(* Logix 5000 project; controller eNod4TSample vendor 1 type 14 code 106 rev 28.12; software revision 28.00; part 2 of 2 *)
(* tags used below, declared in another part *)
   Datas : TeNod4TDatas;
   DatasOUT : SINT[2];
   Command : INT;
   Ready : BOOL;
   Done : BOOL;
   Timeout : BOOL;
   StabWeight : DINT;
   StabTime : DINT;
   Stability : BOOL;
   LoopWStart : BOOL;
   LoopWStartEdge : BOOL;
   LoopWRun : BOOL;
   LoopWSend : BOOL;
   LoopWDone : BOOL;
   MemCounter : DINT;
   TimerOut : TIMER;
   TimerStab : TIMER;
   MemNet : DINT;
   StabOK : BOOL;
(* TeNod4TBlocMain, continued *)

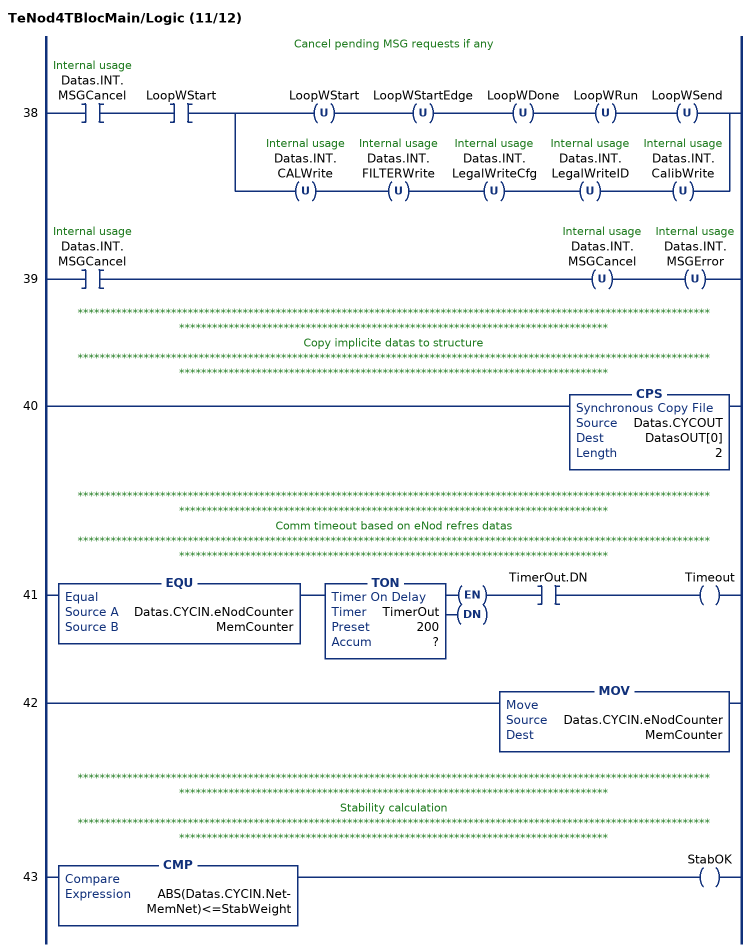
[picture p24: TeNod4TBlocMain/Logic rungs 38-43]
   // Cancel pending MSG requests if any
   38: XIC(Datas.INT.MSGCancel)XIC(LoopWStart)[OTU(LoopWStart) OTU(LoopWStartEdge) OTU(LoopWDone) OTU(LoopWRun) OTU(LoopWSend) ,OTU(Datas.INT.CALWrite) OTU(Datas.INT.FILTERWrite) OTU(Datas.INT.LegalWriteCfg) OTU(Datas.INT.LegalWriteID) OTU(Datas.INT.CalibWrite) ];
   39: XIC(Datas.INT.MSGCancel)OTU(Datas.INT.MSGCancel)OTU(Datas.INT.MSGError);
   // *************************************************************************************************************************************************************************************************
   // Copy implicite datas to structure
   // *************************************************************************************************************************************************************************************************
   40: CPS(Datas.CYCOUT,DatasOUT[0],2);
   // *************************************************************************************************************************************************************************************************
   // Comm timeout based on eNod refres datas
   // *************************************************************************************************************************************************************************************************
   41: EQU(Datas.CYCIN.eNodCounter,MemCounter)TON(TimerOut,?,?)XIC(TimerOut.DN)OTE(Timeout);
   42: MOV(Datas.CYCIN.eNodCounter,MemCounter);
   // *************************************************************************************************************************************************************************************************
   // Stability calculation
   // *************************************************************************************************************************************************************************************************
   43: CMP(ABS(Datas.CYCIN.Net-MemNet)<=StabWeight)OTE(StabOK);
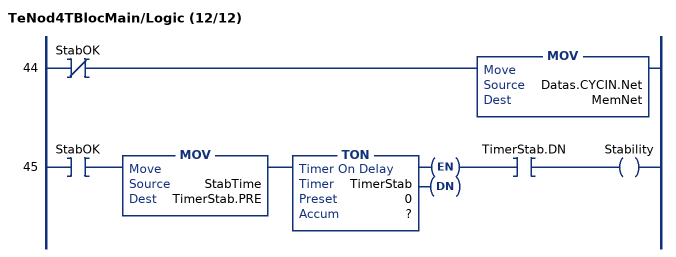
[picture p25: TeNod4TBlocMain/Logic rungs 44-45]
   44: XIO(StabOK)MOV(Datas.CYCIN.Net,MemNet);
   45: XIC(StabOK)MOV(StabTime,TimerStab.PRE)TON(TimerStab,?,?)XIC(TimerStab.DN)OTE(Stability);
END_ROUTINE
END_ADD_ON_INSTRUCTION

VAR_GLOBAL   (* controller tags *)
   Scale1Datas : TeNod4TDatas;
   Scale1R : MESSAGE;
        MessageParameters(ServiceCode := 16#000e, DestinationTag := Scale1Datas.MSGBuffer, ...)
   Scale1W : MESSAGE;
        MessageParameters(ServiceCode := 16#0010, LocalElement := Scale1Datas.MSGBuffer, ...)
END_VAR

PROGRAM MainProgram   (* main routine MainRoutine *)
VAR
   Output1 : BOOL;
   Output1Toggle : BOOL;
   Scale1Back : TeNod4TBlocBackupRestore;
   Scale1Calib : TeNod4TBlocCalibration := (NumSegment := 1);
   Scale1Filter : TeNod4TBlocFilters;
   Scale1Legal : TeNod4TBlocLegal;
   Scale1Main : TeNod4TBlocMain;
END_VAR

ROUTINE MainRoutine   (* ladder *)
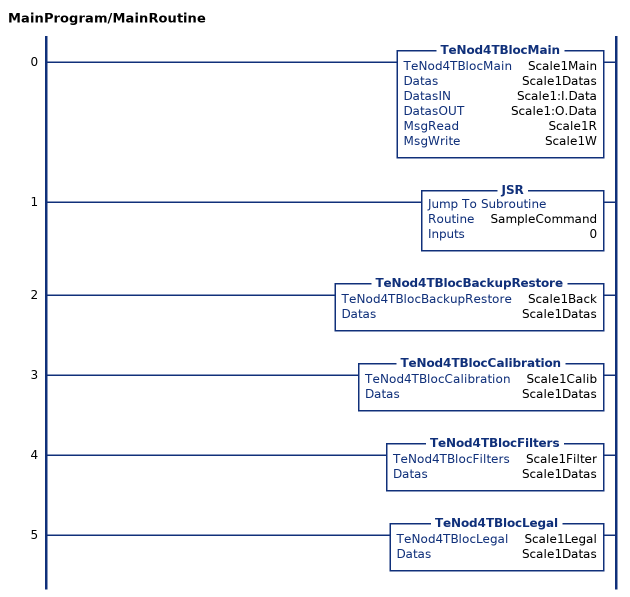
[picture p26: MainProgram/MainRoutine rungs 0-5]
   0: TeNod4TBlocMain(Scale1Main,Scale1Datas,Scale1:I.Data,Scale1:O.Data,Scale1R,Scale1W);
   1: JSR(SampleCommand,0);
   2: TeNod4TBlocBackupRestore(Scale1Back,Scale1Datas);
   3: TeNod4TBlocCalibration(Scale1Calib,Scale1Datas);
   4: TeNod4TBlocFilters(Scale1Filter,Scale1Datas);
   5: TeNod4TBlocLegal(Scale1Legal,Scale1Datas);
END_ROUTINE

ROUTINE SampleCommand   (* ladder *)
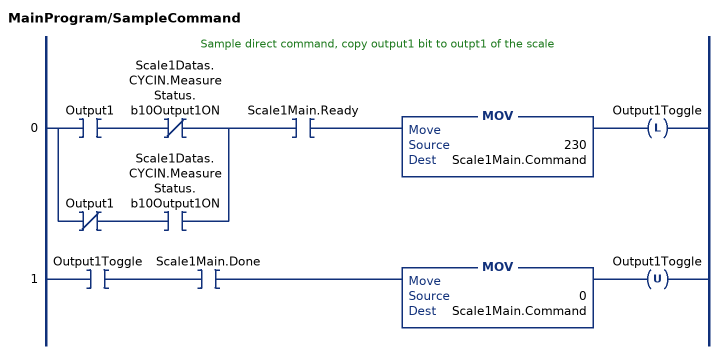
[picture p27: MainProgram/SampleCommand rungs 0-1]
   // Sample direct command, copy output1 bit to outpt1 of the scale
   0: [XIC(Output1) XIO(Scale1Datas.CYCIN.MeasureStatus.b10Output1ON) ,XIO(Output1) XIC(Scale1Datas.CYCIN.MeasureStatus.b10Output1ON) ]XIC(Scale1Main.Ready)MOV(230,Scale1Main.Command)OTL(Output1Toggle);
   1: XIC(Output1Toggle)XIC(Scale1Main.Done)MOV(0,Scale1Main.Command)OTU(Output1Toggle);
END_ROUTINE
END_PROGRAM
